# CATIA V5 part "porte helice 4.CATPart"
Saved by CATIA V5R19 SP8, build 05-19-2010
Part number: porte helice 4
Bounding box of the stored display mesh (mm): x -20 to 20, y -50 to 180, z -20 to 20
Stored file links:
  G:\EU_thinkMotion\CFAO_2010\MMS_groupe2\MMS_groupe2\A reprendre\splanchenault\Planchenault\porte helice 4.CATPart
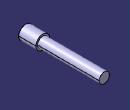
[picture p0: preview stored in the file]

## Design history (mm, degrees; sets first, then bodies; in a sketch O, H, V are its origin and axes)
Body1 (main body)
  Sketch1 on zx-plane, origin (0, 0, 0), H (-1, 0, 0), V (0, 0, 1)
    circle A1 centre (0, 0) radius 15
    point P1 (15, 0)
    radius A1 = 15
    coincidence: A1 P1, P1 H
  Pad1: profile Sketch1, direction (0, 1, 0), length 180
  Sketch2 on start face of Pad1, origin (0, 0, 0), H (1, 0, 0), V (0, 0, 1)
    circle A1 centre (0, 0) radius 20
    radius A1 = 20
  Pad2: profile Sketch2, direction (0, -1, 0), length 50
